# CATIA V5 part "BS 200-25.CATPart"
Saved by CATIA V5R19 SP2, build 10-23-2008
Part number: BS 200-25
Bounding box of the stored display mesh (mm): x -12.497 to 12.497, y -12.358 to 12.358, z 0 to 80
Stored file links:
  C:\Users\Bora\Desktop\3D Katı model\BS serisi\BS 200\BS 200-25.CATPart
  C:\Program Files\Dassault Systemes\B19\intel_a\reffiles\standard\MetricThickPitch.txt
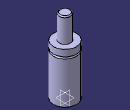
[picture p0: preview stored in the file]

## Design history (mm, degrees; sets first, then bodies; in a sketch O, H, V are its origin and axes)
Body1 (main body)
  Sketch1 on yz-plane, origin (0, 0, 0), H (0, 1, 0), V (0, 0, 1)
    point P1 (6, 79)
    point P3 (6, 79)
    point P5 (12.5, 47)
    point P6 (12.5, 45)
    point P8 (12.5, 45)
    point P9 (12.5, 47)
    line L1 (6, 79) -> (6, 54)
    arc A1 centre (5, 79) radius 1 from (6, 79) to (5, 80) ccw
    arc A2 centre (12.5, 46) radius 1 from (12.5, 47) to (12.5, 45) ccw
    line L2 (12.5, 0) -> (12.5, 45)
    line L3 (12.5, 47) -> (12.5, 54)
    line L4 (5, 80) -> (0, 80)
    point P11 (0, 80)
    line L5 (6, 54) -> (12.5, 54)
    line L6 (12.5, 0) -> (0, 0)
    coincidence: P11 V, P1 P3, P5 P9, P6 P8
    tangency: L4 A1
    horizontal: L5 H, L6 H
  Shaft1: profile Sketch1, axis Sketch1.V, angle 360
  Sketch2 on face of Shaft1 from Sketch1.L6, origin (0, 0, 0), H (1, 0, 0), V (0, -1, 0)
    point P1 (0, 0)
  Hole1: placed by Sketch2, at (0, 0, 0) direction (0, 0, 1), diameter 4.917, depth 4, threaded "M6", thread diameter 6, thread depth 4, pitch 1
